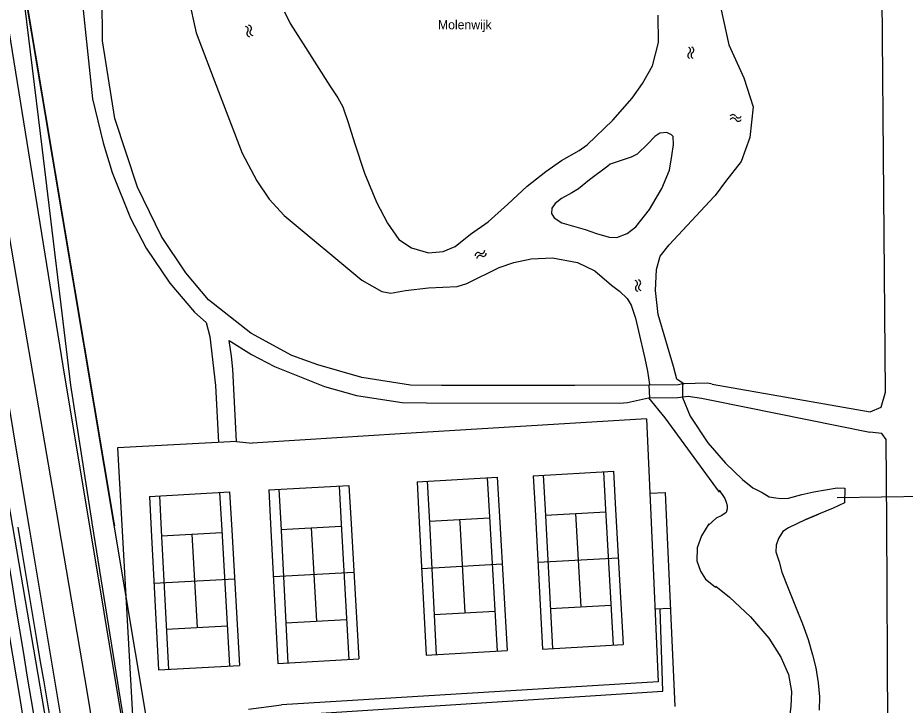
# Model space of a CAD drawing. Extents: x 148816 to 151297, y 399515 to 402500.
# Drawn here: x 149404.6 to 149526, y 400725 to 400819.1 of the extents above; entities that cross this region are included whole.
import ezdxf

# ---------------------------------------------------------------- set-up
doc = ezdxf.new("R2010")
doc.units = 0
for name, color, linetype in [('G01 perceelsgrens', 7, 'Continuous'), ('Q01 Spoorrail  [D] Norm', 7, 'Continuous'), ('Q21 Lichtmast  Gem', 7, 'Continuous'), ('S05 Water  Norm', 7, 'Continuous'), ('T04 Haag heg  [D] Gem', 7, 'Continuous'), ('T09 Insteek water  [T] Norm', 7, 'Continuous'), ('V00 Kant verharding algemeen  [T] Norm', 7, 'Continuous'), ('W10 Duiker  [T] Gem', 7, 'Continuous'), ('Z19 Overige Tekst  [Tekst] Gem', 7, 'Continuous')]:
    doc.layers.add(name, color=color, linetype=linetype)

msp = doc.modelspace()

# ---------------------------------------------------------------- linework, layer by layer
at = {"layer": 'G01 perceelsgrens'}
for points in [[(149474.3, 400500), (149465.62, 400529.89), (149453.09, 400562.24), (149445.47, 400580.02), (149441.93, 400593.24), (149439.07, 400606.36), (149433.29, 400636.6), (149410.86, 400771.43), (149399.43, 400842.23), (149379.26, 400968.4), (149379, 400970.86), (149375.68, 400970.26), (149373.64, 400982.49), (149377.7, 400983.23), (149377.26, 400987.35)], [(149380.85, 400976.67), (149402.17, 400842.5), (149426.33, 400698.43), (149438.5, 400632.51), (149456.12, 400567.45), (149480.52, 400500)]]:
    msp.add_lwpolyline(points, dxfattribs=at)
at = {"layer": 'Q01 Spoorrail  [D] Norm'}
for p, q in [((149364.62, 401000), (149406.05, 400750)), ((149406.05, 400750), (149406.18, 400749.19))]:
    msp.add_line(p, q, dxfattribs=at)
for centre, radius, start, end in [((165820.47, 403491.79), 16643.33, 189.484339, 189.821758), ((156405.27, 401884.74), 7094.13, 189.218769, 190.064919), ((165820.47, 403491.79), 16641.83, 189.485686, 189.821758), ((156405.27, 401884.74), 7095.63, 189.218769, 190.064919)]:
    msp.add_arc(centre, radius, start, end, dxfattribs=at)
at = {"layer": 'Q21 Lichtmast  Gem'}
msp.add_lwpolyline([(149831.23, 399977.82), (149652.8, 400166.23), (149577.93, 400264.8), (149509.93, 400379.6), (149457.52, 400503.12), (149428.83, 400604.19), (149365.19, 400976.02), (149329.8, 401182.82), (149252.91, 401632.09)], dxfattribs=at)
at = {"layer": 'S05 Water  Norm'}
for centre, start, end in [((149435.75, 400817.43), 320.1685, 84.0235), ((149436.17, 400817.6), 320.1685, 84.0235), ((149436.82, 400817.06), 140.1685, 264.0235), ((149436.4, 400816.89), 140.1685, 264.0235), ((149496.23, 400814.6), 302.6066, 66.4616), ((149496.68, 400814.64), 302.6066, 66.4616), ((149496.69, 400813.89), 122.6066, 246.4616), ((149497.14, 400813.92), 122.6066, 246.4616), ((149502.45, 400805.37), 28.5084, 152.3634), ((149502.46, 400804.92), 28.5084, 152.3634), ((149503.2, 400805.78), 208.5084, 332.3634), ((149503.2, 400805.33), 208.5084, 332.3634), ((149467.63, 400786.5), 58.278, 182.133), ((149468.08, 400787.22), 238.278, 2.133), ((149467.86, 400786.11), 58.278, 182.133), ((149468.3, 400786.83), 238.278, 2.133), ((149488.98, 400782.68), 311.2918, 75.1468), ((149489.54, 400782.04), 131.2918, 255.1468), ((149489.41, 400782.79), 311.2918, 75.1468), ((149489.97, 400782.15), 131.2918, 255.1468)]:
    msp.add_arc(centre, 0.425, start, end, dxfattribs=at)
at = {"layer": 'T04 Haag heg  [D] Gem'}
for p, q in [((149402.24, 400842.7), (149417.79, 400750)), ((149490.62, 400764.16), (149456.95, 400762.1)), ((149490.62, 400764.16), (149491.26, 400750)), ((149456.95, 400762.1), (149443.96, 400761.3)), ((149434.58, 400761.09), (149418.3, 400760.19)), ((149418.3, 400760.19), (149420.33, 400723.57)), ((149434.58, 400761.09), (149436.69, 400760.86)), ((149443.96, 400761.3), (149436.69, 400760.86)), ((149491.03, 400754.01), (149493.18, 400754.09)), ((149493.18, 400754.09), (149493.36, 400750)), ((149417.79, 400750), (149417.87, 400749.52)), ((149491.26, 400750), (149492.24, 400728.17)), ((149493.36, 400750), (149494.49, 400724.81)), ((149493.89, 400738.21), (149491.79, 400738.15)), ((149492.24, 400728.17), (149440.71, 400725.05)), ((149436.21, 400724.45), (149440.71, 400725.05))]:
    msp.add_line(p, q, dxfattribs=at)
at = {"layer": 'T09 Insteek water  [T] Norm'}
for p, q in [((149501.45, 400796.65), (149500, 400794.72)), ((149500, 400794.72), (149499.9, 400794.59)), ((149490.95, 400768.76), (149491.05, 400767.06)), ((149495.57, 400768.96), (149495.57, 400767.11)), ((149490.9, 400767.05), (149493.12, 400764.31)), ((149495.57, 400767.11), (149496.61, 400764.53)), ((149493.12, 400764.31), (149500.57, 400754.15)), ((149496.61, 400764.53), (149499.03, 400760.87)), ((149499.03, 400760.87), (149501.45, 400758.11)), ((149501.45, 400758.11), (149503.77, 400755.87)), ((149503.77, 400755.87), (149505.18, 400754.74)), ((149500.57, 400754.41), (149501.32, 400753.29)), ((149505.18, 400754.74), (149506.45, 400754.08)), ((149511.88, 400753.8), (149513.5, 400754.2)), ((149513.5, 400754.2), (149516.7, 400754.74)), ((149516.7, 400754.74), (149517.77, 400754.69)), ((149517.77, 400754.69), (149517.71, 400752.66)), ((149501.32, 400753.29), (149501.52, 400752.78)), ((149506.45, 400754.08), (149507.41, 400753.52)), ((149507.41, 400753.52), (149508.32, 400753.36)), ((149508.32, 400753.36), (149508.98, 400753.25)), ((149508.98, 400753.25), (149510.05, 400753.3)), ((149510.05, 400753.3), (149511.88, 400753.8)), ((149501.67, 400751.86), (149501.51, 400751.36)), ((149501.52, 400752.78), (149501.67, 400752.32)), ((149501.67, 400752.32), (149501.67, 400751.86)), ((149516.18, 400751.95), (149514.15, 400751.15)), ((149517.71, 400752.66), (149516.18, 400751.95)), ((149500.14, 400750.6), (149499.07, 400749.59)), ((149500.95, 400750.95), (149500.14, 400750.6)), ((149501.51, 400751.36), (149500.95, 400750.95)), ((149514.15, 400751.15), (149512.42, 400750.39)), ((149512.42, 400750.39), (149514.15, 400751.15)), ((149414.18, 400726.64), (149410.27, 400749.69)), ((149414.79, 400749.95), (149418.7, 400725.56)), ((149499.17, 400749.8), (149498.13, 400748.18)), ((149498.13, 400748.18), (149497.55, 400746.53)), ((149497.55, 400746.53), (149497.5, 400744.76)), ((149497.5, 400744.76), (149498.01, 400743.32)), ((149498.01, 400743.32), (149498.72, 400742.25)), ((149498.72, 400742.25), (149500, 400741.17)), ((149500, 400741.17), (149500.07, 400741.11)), ((149420.27, 400690.04), (149414.18, 400726.64)), ((149418.7, 400725.56), (149426.17, 400680.22))]:
    msp.add_line(p, q, dxfattribs=at)
for points in [[(149410.22, 400750), (149404.85, 400781.36), (149402.39, 400795.83), (149396.59, 400829.72), (149392.64, 400852.46), (149385.67, 400895.78), (149378.85, 400937.56)], [(149385.62, 400929.69), (149388.89, 400913.22), (149395.2, 400884.59), (149399.67, 400864.36), (149401.88, 400852.18), (149404.46, 400829.74), (149407.97, 400800.98), (149411.84, 400768.77), (149414.78, 400750)], [(149500, 400823.93), (149501.88, 400815.33), (149503.93, 400810.84), (149505.23, 400806.88), (149504.77, 400802.69), (149503.58, 400799.37), (149501.45, 400796.65)], [(149427.99, 400821.8), (149429.03, 400817), (149432.08, 400808.96), (149435.33, 400800.53), (149437.36, 400796.72), (149439.04, 400794.21), (149441.07, 400791.98), (149451.71, 400783.14), (149454.42, 400781.6), (149455.67, 400781.37), (149457.67, 400781.75), (149460.82, 400782.1), (149464.75, 400782.26), (149466.05, 400782.71), (149470.49, 400784.87), (149472.49, 400785.56), (149474.85, 400786.06), (149477.77, 400786.19), (149481.18, 400785.58), (149483.56, 400784.42), (149485.85, 400782.46), (149486.96, 400781.62), (149488, 400780.66), (149488.54, 400779.72), (149489.12, 400777.94), (149489.53, 400776.17), (149490.39, 400772.41), (149490.77, 400770.68), (149491.03, 400768.86)], [(149441.14, 400819.85), (149441.92, 400818.25), (149443.68, 400815.51), (149447.31, 400809.72), (149448.4, 400808.12), (149449.08, 400806.85), (149449.85, 400804.72), (149450.68, 400801.95), (149452.06, 400797.81), (149453.71, 400793.8), (149455.21, 400790.96), (149456.76, 400788.73), (149458.51, 400787.56), (149460.82, 400786.88), (149462.8, 400787.08), (149464.47, 400787.76), (149466.55, 400789.44), (149468.99, 400791.14), (149471.65, 400793.53), (149474.32, 400795.99), (149476.86, 400798.04), (149478.99, 400799.52), (149481.4, 400800.91), (149482.51, 400801.67), (149486.04, 400805.05), (149488.65, 400808.07), (149490.1, 400810.05), (149491.47, 400812.49), (149492.26, 400815.66), (149492.23, 400819.39)], [(149494.06, 400803.05), (149493.4, 400803.35), (149492.46, 400803.25), (149491.75, 400802.82), (149490.81, 400801.8), (149489.37, 400800.41), (149488.55, 400799.97), (149485.66, 400799.01), (149485.36, 400798.76), (149482.82, 400796.88), (149481.35, 400795.66), (149480.41, 400795.08), (149479.01, 400794.31), (149478.15, 400793.65), (149477.7, 400792.99), (149477.62, 400792.28), (149478, 400791.7), (149479.07, 400790.99), (149482.26, 400790.08), (149483.79, 400789.54), (149485.51, 400789.04), (149486.58, 400788.98), (149487.98, 400789.54), (149489.17, 400790.46), (149491.05, 400792.84), (149492.74, 400795.71), (149493.76, 400798.22)], [(149493.76, 400798.22), (149494.11, 400800.15), (149494.32, 400801.73), (149494.29, 400802.82), (149494.06, 400803.05)], [(149495.77, 400768.91), (149494.76, 400769.59), (149494.33, 400771.34), (149492.24, 400778.45), (149491.86, 400781.73), (149492.01, 400784.62), (149492.49, 400786.45), (149493.71, 400787.97), (149499.9, 400794.59)], [(149410.27, 400749.69), (149410.22, 400750)], [(149414.78, 400750), (149414.79, 400749.95)], [(149512.42, 400750.39), (149510.05, 400749.28), (149509.27, 400748.76), (149508.67, 400747.79), (149508.38, 400746.87), (149508.31, 400745.96), (149508.76, 400744.59), (149509.16, 400743.17), (149509.92, 400741.23), (149511.02, 400738.48), (149511.96, 400736.1), (149512.75, 400733.96), (149513.33, 400731.88), (149513.78, 400730.08), (149514.11, 400728.03), (149514.29, 400726.13), (149514.23, 400724.3)], [(149500.11, 400741.27), (149501.96, 400739.77), (149504.86, 400737.09), (149507.34, 400734.15), (149508.99, 400731.55), (149510.06, 400729.18), (149510.47, 400726.87), (149510.37, 400724.79), (149510.04, 400722.35), (149509.53, 400720.19), (149508.8, 400718.07), (149507.49, 400714.48), (149506.31, 400711.6), (149505.27, 400709.12), (149504.03, 400706.78), (149502.51, 400704.07), (149501.14, 400701.87), (149500.07, 400700.23)]]:
    msp.add_lwpolyline(points, dxfattribs=at)
at = {"layer": 'V00 Kant verharding algemeen  [T] Norm'}
for p, q in [((149416.24, 400815.88), (149416.16, 400823.19)), ((149523.32, 400767.84), (149522.88, 400822.04)), ((149413.6, 400820.1), (149414.87, 400807.96)), ((149417.92, 400805.27), (149416.24, 400815.88)), ((149414.87, 400807.96), (149416.32, 400801.95)), ((149421.02, 400795.88), (149417.92, 400805.27)), ((149416.32, 400801.95), (149417.56, 400797.86)), ((149417.56, 400797.86), (149420.05, 400791.62)), ((149424.29, 400789.13), (149421.02, 400795.88)), ((149420.05, 400791.62), (149422.21, 400787.53)), ((149427.62, 400784.16), (149424.29, 400789.13)), ((149422.21, 400787.53), (149425.44, 400782.73)), ((149430.74, 400780.45), (149427.62, 400784.16)), ((149425.44, 400782.73), (149428.82, 400778.78)), ((149436.53, 400775.91), (149430.74, 400780.45)), ((149428.82, 400778.78), (149430.39, 400777.35)), ((149430.39, 400777.35), (149430.9, 400775.43)), ((149430.9, 400775.43), (149431.69, 400768.75)), ((149433.89, 400772.76), (149433.54, 400774.87)), ((149433.54, 400774.87), (149436.61, 400772.96)), ((149442.14, 400772.86), (149436.53, 400775.91)), ((149434.05, 400770.96), (149433.89, 400772.76)), ((149436.61, 400772.96), (149439.76, 400771.32)), ((149445.67, 400771.54), (149442.14, 400772.86)), ((149439.76, 400771.32), (149446.59, 400768.6)), ((149451.71, 400769.84), (149445.67, 400771.54)), ((149434.57, 400761.09), (149434.05, 400770.96)), ((149431.69, 400768.75), (149432.11, 400760.95)), ((149458.36, 400768.78), (149451.71, 400769.84)), ((149462.6, 400768.75), (149458.36, 400768.78)), ((149480.85, 400768.75), (149462.6, 400768.75)), ((149490.95, 400768.76), (149480.85, 400768.75)), ((149495.01, 400768.83), (149490.95, 400768.76)), ((149495.57, 400768.96), (149495.01, 400768.83)), ((149499.02, 400769.06), (149495.57, 400768.96)), ((149499.63, 400768.93), (149499.02, 400769.06)), ((149499.63, 400768.93), (149521.24, 400765.12)), ((149446.59, 400768.6), (149450.95, 400767.38)), ((149522.71, 400765.75), (149523.32, 400767.84)), ((149450.95, 400767.38), (149457.22, 400766.42)), ((149457.22, 400766.42), (149460.55, 400766.37)), ((149460.55, 400766.37), (149486.92, 400766.32)), ((149486.92, 400766.32), (149488.04, 400766.42)), ((149488.04, 400766.42), (149490.9, 400767.05)), ((149490.9, 400767.05), (149494.91, 400767.1)), ((149494.91, 400767.1), (149496.33, 400767.28)), ((149496.33, 400767.28), (149498.14, 400767)), ((149498.14, 400767), (149499.74, 400766.67)), ((149499.74, 400766.67), (149521.18, 400762.37)), ((149521.24, 400765.12), (149522.71, 400765.75)), ((149522.82, 400762.15), (149521.18, 400762.37)), ((149523.41, 400761.34), (149522.82, 400762.15)), ((149523.48, 400750), (149523.41, 400761.34)), ((149475.15, 400756.39), (149486.1, 400757.01)), ((149484.74, 400756.93), (149485.03, 400751.78)), ((149486.1, 400757.01), (149486.4, 400751.78)), ((149459.27, 400755.56), (149470.22, 400756.18)), ((149459.27, 400755.56), (149459.56, 400750)), ((149460.64, 400755.63), (149460.93, 400750)), ((149468.86, 400756.1), (149469.2, 400750)), ((149470.22, 400756.18), (149470.57, 400750)), ((149475.15, 400756.39), (149475.39, 400751.78)), ((149476.52, 400756.47), (149476.76, 400751.78)), ((149422.65, 400753.55), (149433.61, 400754.17)), ((149433.61, 400754.17), (149433.9, 400748.94)), ((149438.99, 400754.44), (149449.94, 400755.05)), ((149438.99, 400754.44), (149439.23, 400749.82)), ((149440.36, 400754.51), (149440.6, 400749.82)), ((149448.58, 400754.98), (149448.87, 400749.82)), ((149449.94, 400755.05), (149450.24, 400749.82)), ((149422.65, 400753.55), (149422.89, 400748.94)), ((149424.02, 400753.62), (149424.26, 400748.94)), ((149432.24, 400754.09), (149432.53, 400748.94)), ((149475.39, 400751.78), (149476.39, 400732.66)), ((149476.76, 400751.78), (149477.76, 400732.73)), ((149485.03, 400751.78), (149486.08, 400733.2)), ((149486.4, 400751.78), (149487.44, 400733.28)), ((149460.93, 400750.15), (149469.17, 400750.62)), ((149476.8, 400750.99), (149485.05, 400751.45)), ((149480.93, 400751.22), (149481.65, 400738.45)), ((149439.23, 400749.82), (149440.23, 400730.7)), ((149440.6, 400749.82), (149441.6, 400730.77)), ((149440.64, 400749.03), (149448.89, 400749.5)), ((149444.77, 400749.26), (149445.49, 400736.49)), ((149448.87, 400749.82), (149449.92, 400731.24)), ((149450.24, 400749.82), (149451.28, 400731.32)), ((149459.56, 400750), (149460.51, 400731.82)), ((149460.93, 400750), (149461.88, 400731.89)), ((149465.05, 400750.39), (149465.08, 400750)), ((149465.08, 400750), (149465.78, 400737.62)), ((149469.2, 400750), (149470.2, 400732.37)), ((149470.57, 400750), (149471.57, 400732.45)), ((149523.97, 400665.97), (149523.48, 400750)), ((149422.89, 400748.94), (149423.89, 400729.81)), ((149424.26, 400748.94), (149425.26, 400729.89)), ((149424.31, 400748.15), (149432.55, 400748.61)), ((149428.44, 400748.38), (149429.16, 400735.61)), ((149432.53, 400748.94), (149433.58, 400730.36)), ((149433.9, 400748.94), (149434.95, 400730.44)), ((149475.77, 400744.54), (149486.77, 400745.14)), ((149439.61, 400742.58), (149450.61, 400743.19)), ((149459.89, 400743.71), (149470.89, 400744.31)), ((149423.27, 400741.7), (149434.28, 400742.3)), ((149477.47, 400738.22), (149485.77, 400738.68)), ((149461.59, 400737.38), (149469.89, 400737.85)), ((149492.88, 400726.92), (149492.51, 400738.17)), ((149441.31, 400736.26), (149449.61, 400736.73)), ((149424.98, 400735.37), (149433.27, 400735.84)), ((149460.51, 400731.82), (149471.57, 400732.45)), ((149476.39, 400732.66), (149487.44, 400733.28)), ((149440.23, 400730.7), (149451.28, 400731.32)), ((149423.89, 400729.81), (149434.95, 400730.44)), ((149439.77, 400723.48), (149492.88, 400726.92))]:
    msp.add_line(p, q, dxfattribs=at)
at = {"layer": 'W10 Duiker  [T] Gem'}
msp.add_line((149516.72, 400753.43), (149563.36, 400754.03), dxfattribs=at)

# ---------------------------------------------------------------- texts
at = {"layer": 'Z19 Overige Tekst  [Tekst] Gem'}
msp.add_text('Molenwijk', height=1.25, rotation=360, dxfattribs=at).set_placement((149462.11, 400817.48))

doc.saveas('drawing.dxf')
